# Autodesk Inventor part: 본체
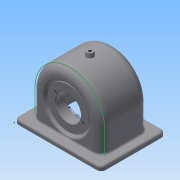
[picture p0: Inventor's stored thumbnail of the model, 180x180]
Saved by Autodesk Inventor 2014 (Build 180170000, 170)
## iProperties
Created: 2015-09
Part Number: 본체
Material: 일반
Document SubType Name: Modeling
Designer: net
Density: 1 g/cm^3
Appearance: 기본값
Author: net
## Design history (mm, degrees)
sketch "스케치1"
  geometry: L1 (0, 0)-(140, 0); L2 (140, 0)-(140, 104); L3 (140, 104)-(0, 104); L4 (0, 104)-(0, 0)
  constraints: 8 end point, 2 parallel, 1 horizontal, 1 perpendicular
  dimensions: "d0" = 140 distance of L3.end L2.end; "d1" = 104 distance of L2.end L1.end
extrude "돌출1" new body sketch "스케치1" distance "d2" = 7; taper "d3" = 0 deg
node "작업 평면1"
sketch "스케치2"
  geometry: L1 (140, 0)-(0, 0) reference; L2 (0, 0)-(0, 7) reference; L3 (140, 7)-(0, 7) reference; L4 (140, 0)-(140, 7) reference; L5 (14, 47)-(126, 47); L6 (140, 0)-(0, 0) reference; L7 (70, 0)-(70, 47); L8 (14, 47)-(14, 7); L9 (126, 47)-(126, 7); L10 (121, 47)-(121, 0); L11 (19, 47)-(19, 0); L12 (19, 0)-(121, 0); A1 r 56 centre (70, 47) between (126, 47) and (14, 47); A2 r 51 centre (70, 47) between (121, 47) and (19, 47)
  constraints: 14 end point, 4 point on circle, 4 point on line, 3 vertical, 2 centre point, 2 horizontal, 2 midpoint, 2 parallel, 2 tangent
  dimensions: "d4" = 47 distance between parallel lines of L1 L5; "d7" = 56 radius of A1; "d11" = 14 distance between parallel lines of L4 L9; "d12" = 5 radial gap between concentric circles of A2 A1; "d13" = 5 distance between parallel lines of L11 L8; "d14" = 5 distance between parallel lines of L9 L10; "d15" = 40 distance from line of A2.start L3; "d16" = 40 distance from line of L10.start L3; "d18" = 40 distance from line of A2.end L3; "d19" = 40 distance from line of L11.start L3
  node "투영된 루프1"
extrude "돌출2" join sketch "스케치2" stored distance "d21" = 77; taper "d22" = 0 deg
sketch "스케치3"
  geometry: L1 (19, 47)-(19, 0) reference; L2 (121, 47)-(121, 0) reference; L3 (19, 0)-(121, 0) reference; A1 r 51 centre (70, 47) between (121, 47) and (19, 47) reference; 1 further point
extrude "돌출3" cut sketch "스케치3" stored distance "d23" = 66; taper "d24" = 0 deg
node "작업 평면2"
sketch "스케치4"
  geometry: 1 further point
sketch "스케치5"
  geometry: 1 further point
node "작업 평면3"
sketch "스케치9"
  geometry: L1 (14, 47)-(14, 7) reference; L2 (126, 7)-(14, 7) reference; L3 (126, 7)-(126, 47) reference; C1 r 28 at (70, 47); A1 r 56 centre (70, 47) between (126, 47) and (14, 47) reference; 1 further point
  constraints: 1 centre point, 1 coincident
  dimensions: "d25" = 56 diameter of C1
sketch "스케치11"
  geometry: L1 (19, 0)-(19, -47) reference; L2 (121, 0)-(19, 0) reference; L3 (121, -47)-(121, 0) reference; C1 r 31 at (70, -47); A1 r 51 centre (70, -47) between (19, -47) and (121, -47) reference; 1 further point
  constraints: 1 centre point, 1 coincident
  dimensions: "d28" = 62 diameter of C1
extrude "돌출5" join sketch "스케치11" distance "d29" = 10; taper "d30" = 0 deg
sketch "스케치12"
  geometry: C1 r 31 at (0, 0) reference; 1 further point
node "작업 평면4"
sketch "스케치13"
  geometry: L1 (-103, 13.5)-(-47, 13.5) reference; L2 (-7, 13.5)-(-47, 13.5) reference; L3 (0, 104)-(0, 0) reference; L4 (-16, 100.5)-(-78, 100.5) reference
sketch "스케치14"
  geometry: L1 (121, 0)-(121, -47) reference; L2 (19, 0)-(121, 0) reference; L3 (19, -47)-(19, 0) reference; L4 (14, -47)-(14, -7) reference; L5 (126, -7)-(14, -7) reference; L6 (126, -7)-(126, -47) reference; C1 r 28 at (70, -47); A1 r 51 centre (70, -47) between (19, -47) and (121, -47) reference; A2 r 56 centre (70, -47) between (14, -47) and (126, -47) reference; 1 further point
  constraints: 1 centre point, 1 coincident
  dimensions: "d31" = 56 diameter of C1
  node "투영된 루프4"
sketch "스케치15"
  geometry: L1 (121, 0)-(121, -47) reference; L2 (19, 0)-(121, 0) reference; L3 (19, -47)-(19, 0) reference; C1 r 33 at (70, -47); A1 r 51 centre (70, -47) between (19, -47) and (121, -47) reference; 1 further point
  constraints: 1 centre point, 1 coincident
  dimensions: "d32" = 66 diameter of C1
node "작업 평면5"
sketch "스케치16"
  geometry: L1 (13.5, 103)-(13.5, 47) reference; L2 (19, 98)-(19, 47) reference; L3 (19, 7)-(19, 47) reference; L4 (19, 47)-(85, 47); L5 (32.5, 75)-(32.5, 67); L6 (32.5, 67)-(16.5, 67); L7 (32.5, 75)-(13.5, 90.943); L8 (19, 79.801)-(13.5, 84.416); L9 (16.5, 80)-(16.5, 67); L10 (16.5, 80)-(18.763, 80); L11 (13.5, 90.943)-(13.5, 84.416); L12 (32.5, 67)-(32.5, 47); L13 (16.5, 67)-(16.5, 47); L14 (16.5, 47)-(19, 47); L15 (13.5, 90.943)-(13.5, 84.416); L16 (16.5, 47)-(32.5, 47); L17 (13.5, 84.416)-(13.5, 47); L18 (13.5, 47)-(19, 47); L19 (13.5, 84.416)-(13.5, 47); 1 further point
  constraints: 32 end point, 8 vertical, 6 horizontal, 5 point on line, 1 parallel
  dimensions: "d35" = 5 distance between parallel lines of L8 L7; "d36" = 16 distance between parallel lines of L9 L5; "d37" = 3 distance between parallel lines of L9 L1; "d38" = 56 diameter of L5.start L4; "d39" = 66 diameter of L10 L4; "d40" = 40 diameter of L6 L4; "d41" = 50 deg angle of L5 L7
revolve "회전1" stored, may be unused: angle "d42" = 90 deg
revolve "회전2" stored, may be unused: angle "d43" = 90 deg
hole "구멍1" diameter "d46" = 40; stored, may be unused: countersink angle "d50" = 90 deg, drill point angle "d52" = 0 deg; dims "d44" = 10, "d45" = 10, "d47" = 6, "d48" = 4, "d49" = 2, "d51" = 8
fillet "모깎기1" dims "d53" = 0.5
sketch "스케치17"
  geometry: C1 r 20 at (0, 0) reference; A1 r 28 centre (0, 0) between (-28, 0) and (0, 28); 2 further points
  constraints: 3 point on circle, 1 centre point, 1 coincident
  dimensions: "d54" = 56 diameter of A1; "d55" = 108.68763 distance of point (-70, -47) point (28, 0); "d56" = 102.59142 distance of point (-70, -47) A1.end; "d57" = 63.03174 distance of point (-70, -47) A1.start
hole "구멍2" sketch "스케치17" at (0, 28) diameter "d58" = 2.459; stored, may be unused: countersink angle "d62" = 90 deg, drill point angle "d64" = 118 deg; dims "d59" = 7, "d60" = 4, "d61" = 2, "d63" = 9
sketch "스케치18"
  geometry: A1 r 24 centre (0, 0) between (0, -24) and (0, 24); 4 further points
  constraints: 4 point on circle, 2 horizontal alignment, 2 vertical alignment, 1 centre point, 1 coincident
  dimensions: "d68" = 48 diameter of A1
hole "구멍3" sketch "스케치18" at (0, -24), (24, 0), (0, 24), (-24, 0) diameter "d69" = 2.459; stored, may be unused: countersink angle "d73" = 90 deg, drill point angle "d75" = 118 deg; dims "d70" = 6, "d71" = 4, "d72" = 2, "d74" = 8
node "작업 평면6"
sketch "스케치19"
  geometry: L1 (-56, -38.5)-(-56, 38.5) reference; L2 (56, -38.5)-(-56, -38.5) reference; L3 (56, 38.5)-(56, -38.5) reference; L4 (-56, 38.5)-(56, 38.5) reference; L5 (-51, 33)-(-51, -33) reference; L6 (-51, 33)-(51, 33) reference; L7 (51, -33)-(51, 33) reference; L8 (51, -33)-(-51, -33) reference; C1 r 6 at (0, 0); 1 further point
  constraints: 1 centre point
  dimensions: "d76" = 12 diameter of C1; "d77" = 51 distance from line of C1.centre L5; "d78" = 33 distance from line of L6 C1.centre
extrude "돌출6" join sketch "스케치19" distance "d79" = 6; taper "d80" = -10 deg
hole "구멍4" diameter "d83" = 4.459; stored, may be unused: countersink angle "d87" = 90 deg, drill point angle "d89" = 118 deg; dims "d81" = 10, "d82" = 10, "d84" = 6, "d85" = 4, "d86" = 2, "d88" = 8
fillet "모깎기2" dims "d90" = 7
fillet "모깎기3" dims "d91" = 3
fillet "모깎기4" dims "d92" = 14
fillet "모깎기5" dims "d93" = 9
fillet "모깎기6" dims "d94" = 3
chamfer "모따기1" distance "d95" = 1; stored, may be unused: second distance "d96" = 2, angle "d97" = 45 deg
fillet "모깎기7" dims "d98" = 3
sketch "스케치6"
  geometry: L1 (-51, 5.5)-(0, 5.5) reference; L2 (47, 90.5)-(47, -13.5) reference; L3 (47, -13.5)-(40, -13.5) reference; L4 (40, 90.5)-(40, -13.5) reference; L5 (47, 90.5)-(40, 90.5) reference; 1 further point
  node "투영된 루프2"
sketch "스케치7"
  geometry: L1 (14, 47)-(14, 7) reference; L2 (126, 7)-(14, 7) reference; L3 (126, 7)-(126, 47) reference; A1 r 56 centre (70, 47) between (126, 47) and (14, 47) reference; 1 further point
sketch "스케치8"
  geometry: L1 (14, 47)-(14, 7) reference; L2 (126, 7)-(14, 7) reference; L3 (126, 7)-(126, 47) reference; A1 r 56 centre (70, 47) between (126, 47) and (14, 47) reference; 1 further point
node "솔리드1"
pattern_circular "원형 패턴1" dims angle "d66" = 360 deg
node "투영된 루프3"
node "투영된 루프5"
node "투영된 루프6"
other parameters: "d6" = 112
